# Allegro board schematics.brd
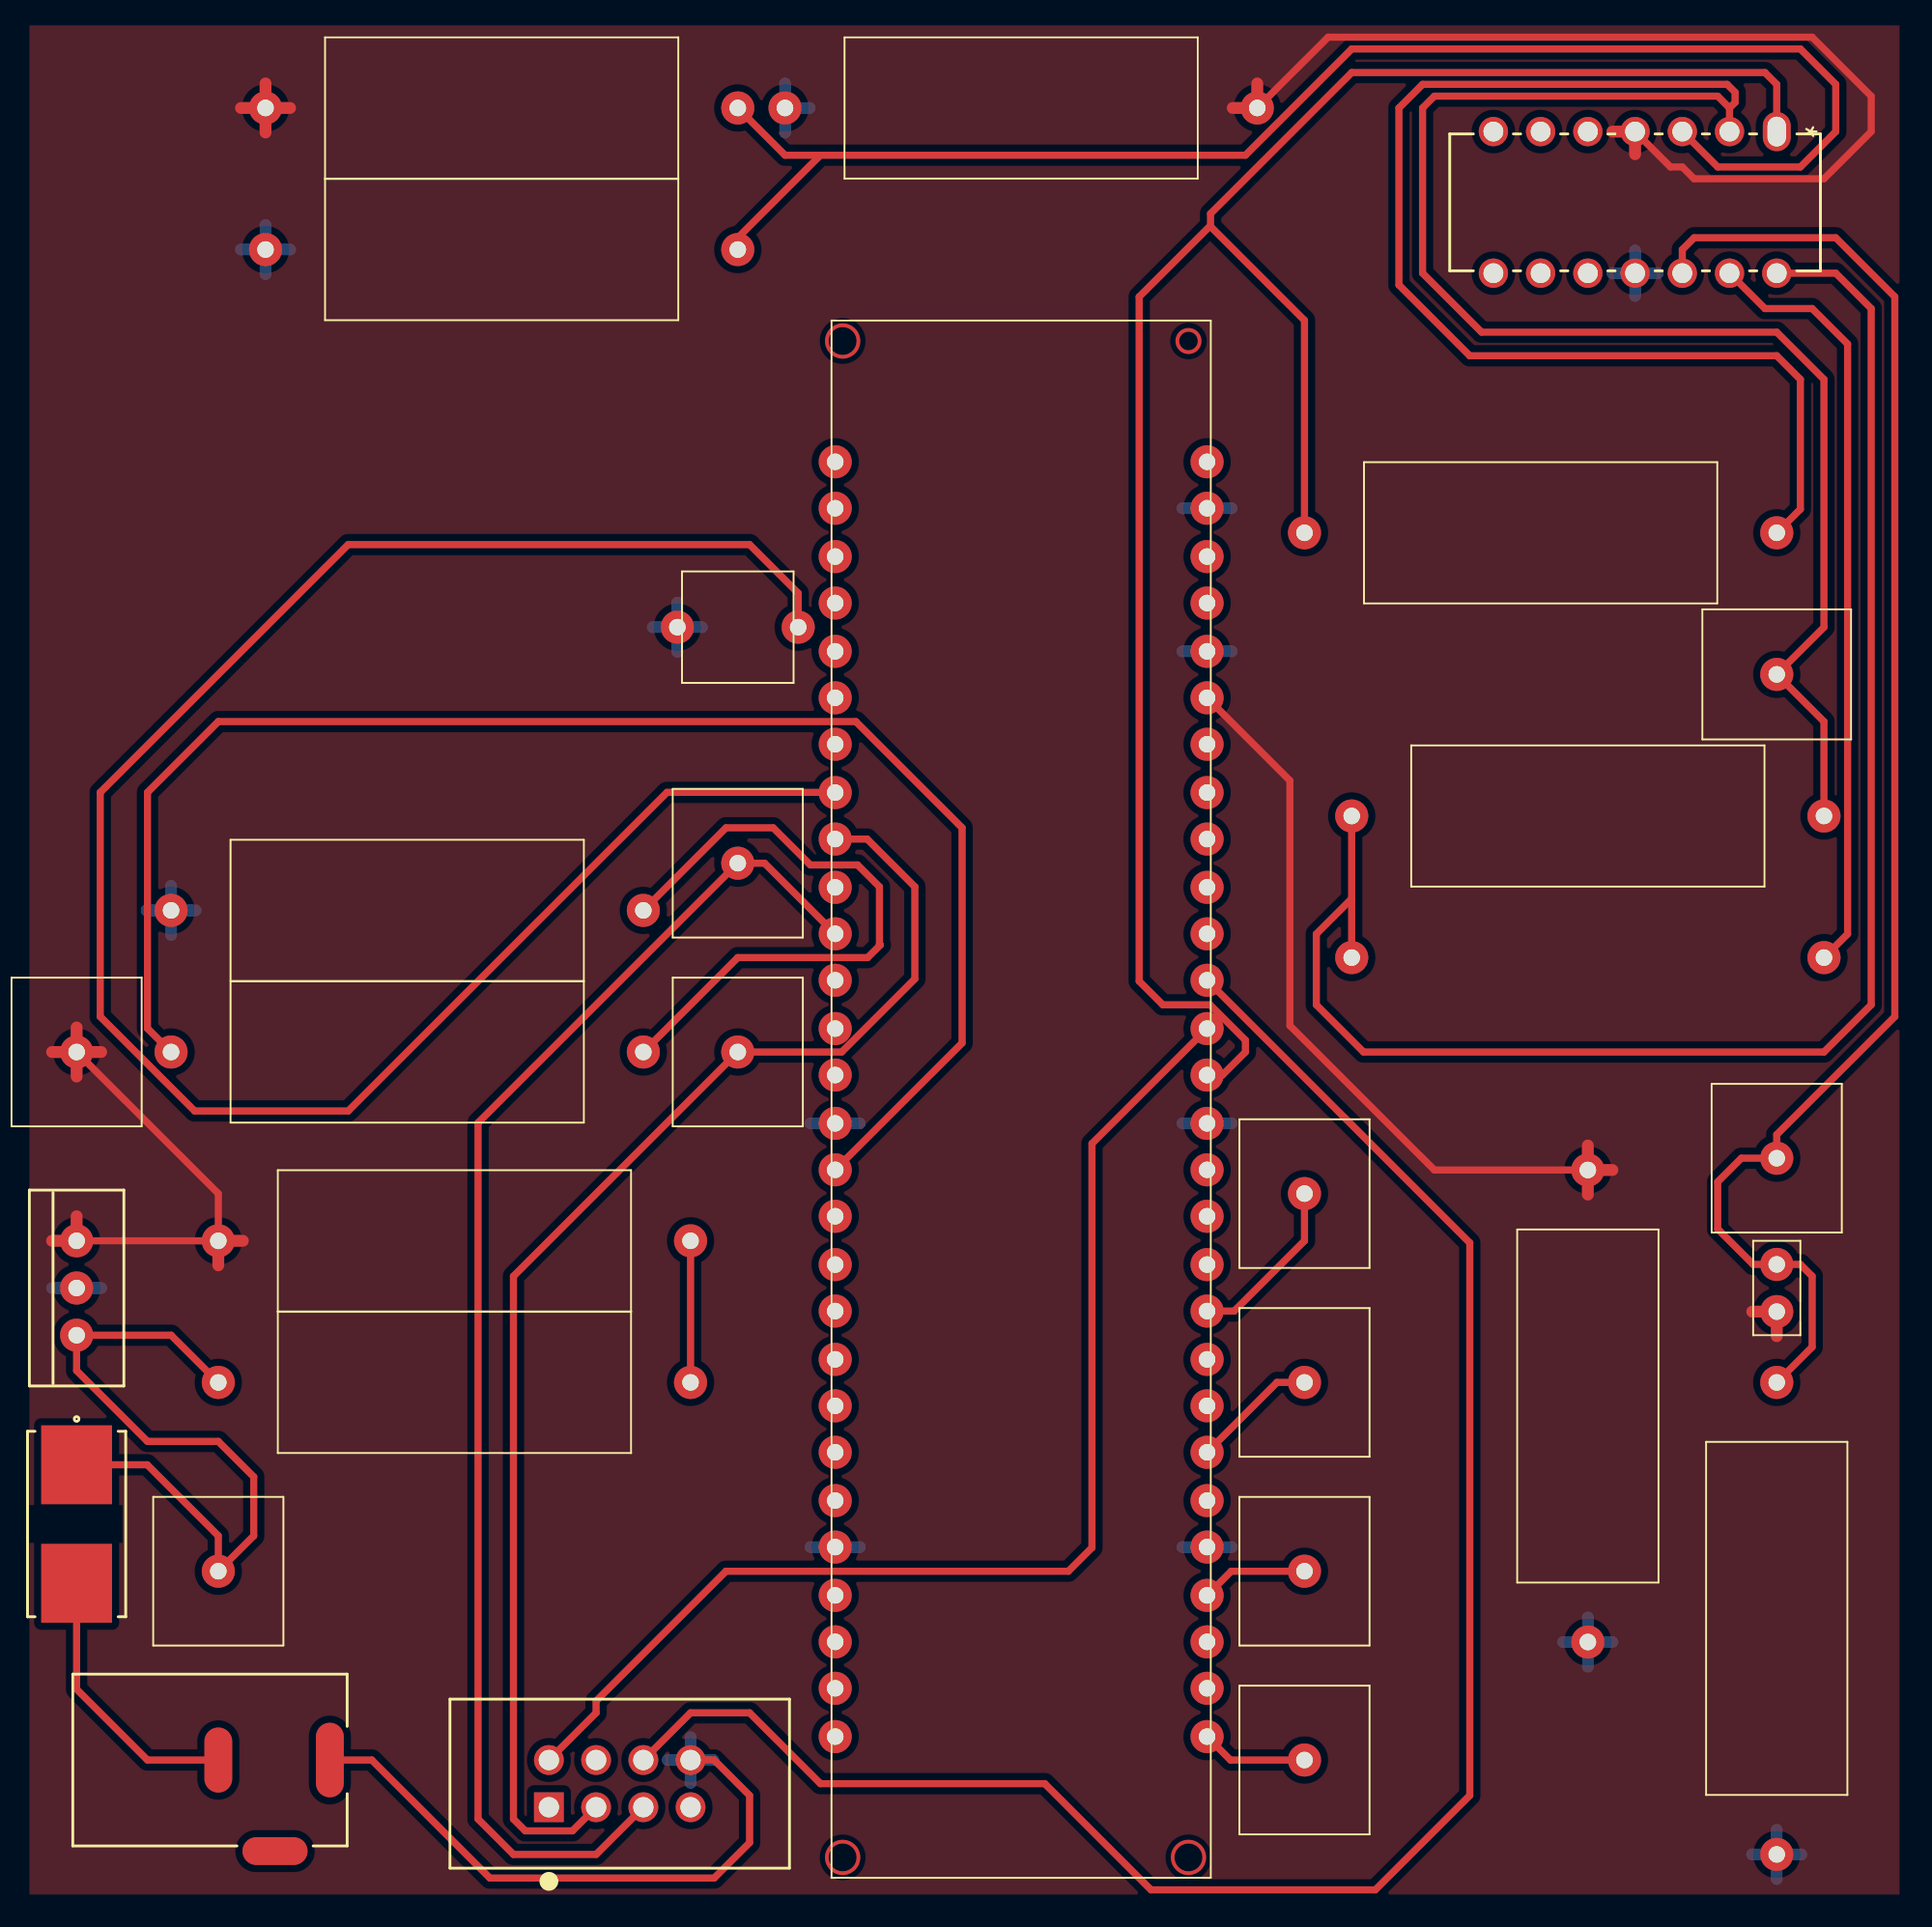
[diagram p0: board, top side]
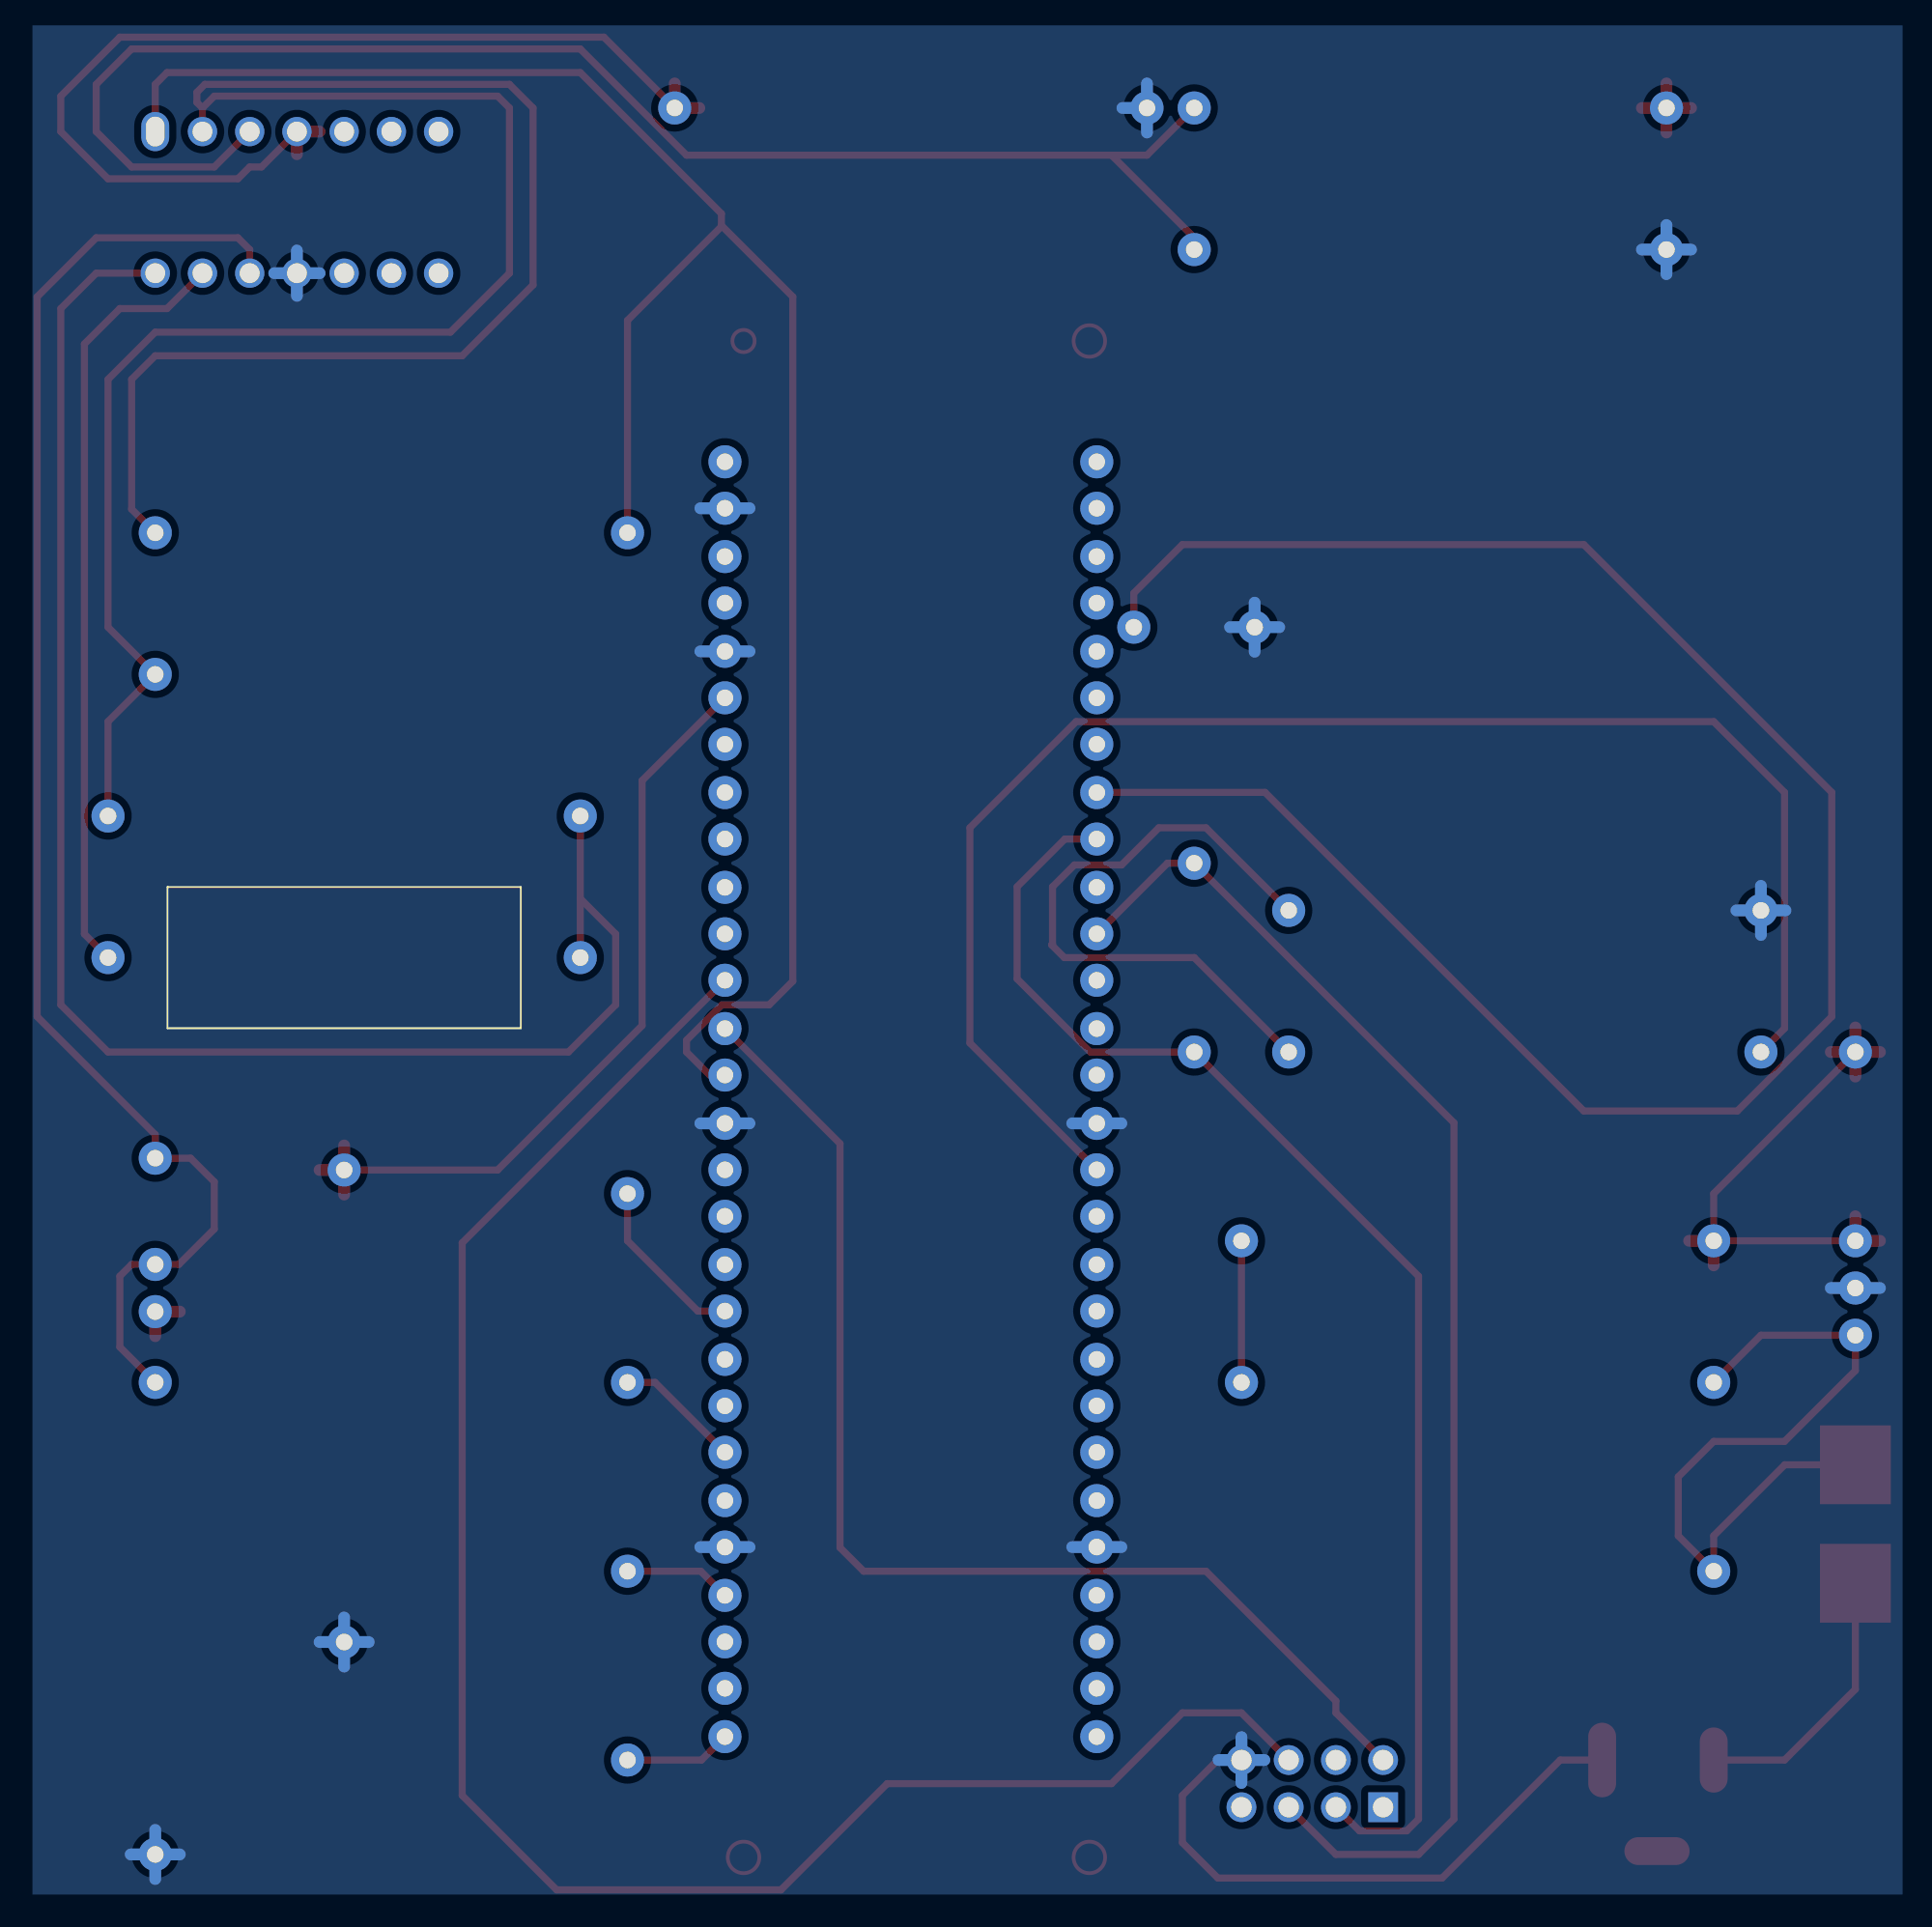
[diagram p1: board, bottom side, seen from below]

No outline. copper layers: TOP, BOTTOM. Coordinates in mm from the lowest, leftmost part position.

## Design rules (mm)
constraint set DEFAULT: min track width 0.127

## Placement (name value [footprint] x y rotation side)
C10  0.1  [RESISTOR_TH]  20.32 22.86 180 top
C11  CAP  [RESISTOR_TH]  20.32 30.48 180 top
C12  0.33 uF 50V  [RESISTOR_TH]  50.8 91.44 180 top
C13  CAP  [RESISTOR_TH]  81.28 21.59 270 top
D3  LED  [RESISTOR_TH]  17.78 48.26 0 top
F2  FUSE 1.5A  [FUSE_01550900M_LTF]  0 15.24 90 top
J22  TestPoint1  [CONNECTORONEPIN]  7.62 12.7 0 top
J23  TestPoint2  [CONNECTORONEPIN]  0 40.64 0 top
J25  TestPoint3  [CONNECTORONEPIN]  91.44 34.92 0 top
J27  TestPoint3  [CONNECTORONEPIN]  91.44 60.96 270 top
J28  TestPoint6  [CONNECTORONEPIN]  35.56 40.64 0 top
J29  SpareGPIO1  [CONNECTORONEPIN]  66.04 33.02 0 top
J30  SpareGPIO2  [CONNECTORONEPIN]  66.04 22.86 0 top
J31  SpareGPIO3  [CONNECTORONEPIN]  66.04 12.7 0 top
J32  SpareGPIO4  [CONNECTORONEPIN]  66.04 2.54 0 top
J33  TestPoint6  [CONNECTORONEPIN]  35.56 50.8 0 top
J34  CONN PCB 8_LS  [CONN_61200821621_WRE]  25.4 0 0 top
J35  B_JACK  [NEB21R_LMB]  7.62 2.54 0 top
PCND3  PIC18F57Q43 Curiosity Nano_LS  [56PINS-PIC]  50.8 38.1 0 top
R8  10k  [RESISTOR_TH]  91.44 10.16 270 top
R9  10k  [RESISTOR_TH]  81.28 45.72 180 bottom
R10  10k  [RESISTOR_TH]  81.28 53.34 0 top
R11  RESISTOR  [RESISTOR_TH]  78.74 68.58 0 top
R12  10k  [RESISTOR_TH]  22.86 91.44 0 top
R13  10k  [RESISTOR_TH]  22.86 83.82 180 top
R15  220  [RESISTOR_TH]  17.78 40.64 0 top
SW6  SW SPST  [PUSHBUTTON]  35.56 63.5 0 top
U11  VR_LS  [TO220-3_ONS]  0 25.4 90 top
U12  10kOhms-20kOhms  [HDR_1X02_2]  91.44 27.94 0 top
U14  MCP6004  [SOIC14-N_MC_MCH]  91.44 90.17 270 top

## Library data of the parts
C10 C11 = MKP1839410084HQ
C12 C13 = CAP
D3 = LED
F2 = FUSE/SM: User Part Number: PN; Tolerance: TOL
J22 J23 J25 J27-J33 = CON1
J34 = CONN PCB 8_2: User Part Number: PN; Tolerance: TOL
J35 = B_JACK: User Part Number: PN; Tolerance: TOL
PCND3 = PIC18F57Q10_18
R8-R13 R15 = RESISTOR
SW6 = SW SPST
U11 = VR_LS_11: User Part Number: PN; Tolerance: TOL
U12 = FLEX_SENSOR_FS_L_095_103_RH_0
U14 = MCP6004_0: User Part Number: PN; Tolerance: TOL

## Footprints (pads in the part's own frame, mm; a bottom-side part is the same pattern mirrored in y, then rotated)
56PINS-PIC
  round 1.778 hole 0.889: 1(-10,34.3) 2(-10,31.8) 3(-10,29.2) 4(-10,26.7) 5(-10,24.1) 6(-10,21.6) 7(-10,19.1) 8(-10,16.5) 9(-10,14) 10(-10,11.4) 11(-10,8.9) 12(-10,6.4) 13(-10,3.8) 14(-10,1.3) 15(-10,-1.3) 16(-10,-3.8) 17(-10,-6.3) 18(-10,-8.9) 19(-10,-11.4) 20(-10,-14) 21(-10,-16.5) 22(-10,-19) 23(-10,-21.6) 24(-10,-24.1) 25(-10,-26.7) 26(-10,-29.2) 27(-10,-31.7) 28(-10,-34.3) 29(10,-34.3) 30(10,-31.7) 31(10,-29.2) 32(10,-26.7) 33(10,-24.1) 34(10,-21.6) 35(10,-19) 36(10,-16.5) 37(10,-14) 38(10,-11.4) 39(10,-8.9) 40(10,-6.3) 41(10,-3.8) 42(10,-1.3) 43(10,1.3) 44(10,3.8) 45(10,6.4) 46(10,8.9) 47(10,11.4) 48(10,14) 49(10,16.5) 50(10,19.1) 51(10,21.6) 52(10,24.1) 53(10,26.7) 54(10,29.2) 55(10,31.8) 56(10,34.3)
CONN_61200821621_WRE
  rect 1.6x1.6 hole 1.092: 1(0,0)
  round 1.6 hole 1.092: 2(0,2.54) 3(2.54,0) 4(2.54,2.54) 5(5.08,0) 6(5.08,2.54) 7(7.62,0) 8(7.62,2.54)
CONNECTORONEPIN
  round 1.778 hole 0.889: 1(0,0)
FUSE_01550900M_LTF
  rect 4.242x3.81 smd: 1(-3.188,0) 2(3.188,0)
HDR_1X02_2
  round 1.778 hole 0.889: 1(0,1.27) 2(0,-1.27)
NEB21R_LMB
  oval 1.499x3.505 smd: 1(0,0)
  oval 1.499x4.013 smd: 2(6,0)
  oval 3.505x1.499 smd: 3(3.05,-4.9)
PUSHBUTTON
  round 1.778 hole 0.889: 1(-3.25,0) 2(3.25,0)
RESISTOR_TH
  round 1.778 hole 0.889: 1(-12.7,0) 2(12.7,0)
SOIC14-N_MC_MCH
  oval 2.108x1.499 hole 1.6x0.991: 1(0,0)
  round 1.575 hole 1.067: 2(0,-2.54) 3(0,-5.08) 4(0,-7.62) 5(0,-10.16) 6(0,-12.7) 7(0,-15.24) 8(7.62,-15.24) 9(7.62,-12.7) 10(7.62,-10.16) 11(7.62,-7.62) 12(7.62,-5.08) 13(7.62,-2.54) 14(7.62,0)
TO220-3_ONS
  round 1.778 hole 0.889: 1(0,0) 2(2.54,0) 3(5.08,0)

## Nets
5V: C11.2 C12.1 C13.1 J23.1 PCND3.51(VTG) R12.1 U11.3(VOUT) U12.2(VIN) U14.4
GND: C12.2 C13.2 D3.1(CATHODE) J34.8 J35.2 PCND3.15 PCND3.24 PCND3.33 PCND3.42 PCND3.52 PCND3.55 R8.2 R13.2 SW6.1 U11.2 U14.11(VSS)
FLEX_SENSOR_READINGS: PCND3.43 R11.1 U14.1
LED: PCND3.16 R15.1
PB_DEBUG: PCND3.8 SW6.2
PIN_2: J34.2 PCND3.44
PIN_3: J28.1 J34.3 PCND3.9
PIN_5: J33.1 J34.5 PCND3.11
PIN_6: J34.6 PCND3.45
STRAIN_OUT_RAW: J25.1 R8.1 U12.1 U14.12
N106824: C10.2 F2.2 J22.1 U11.1
N106956: C10.1 C11.1
N108303: R9.1 U14.13
N108331: R9.2 R10.1 U14.14
N108415: J27.1 R10.2 R11.2 U14.2
N108457: R12.2 R13.1 U14.3
N113032: J30.1 PCND3.35
N114337: J31.1 PCND3.32
N114341: J32.1 PCND3.29
N122941: F2.1 J35.1
N1137531: D3.2 R15.2
N11281237: J29.1 PCND3.38

Pads without a net: J34 1 4 7; J35 3; PCND3 1 2 3 4 5 6 7 10 12 13 14 17 18 19 20 21 22 23 25 26 27 28 30 31 34 36 37 39 40 41 46 47 48 49 50 53 54 56; U14 5 6 7 8 9 10

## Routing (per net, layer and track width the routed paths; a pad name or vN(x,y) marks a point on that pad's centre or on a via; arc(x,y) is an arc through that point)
5V: length 140.4
  TOP w0.127: PCND3.51 61.36,59.7
  TOP w0.381: C12.1 67.31,95.25 93.34,95.25 96.52,92.07 96.52,90.17 93.98,87.63 87,87.63 86.36,88.26 85.72,88.26 U14.4 ; PCND3.51 65.25,55.25 65.25,42.06 73.02,34.29 C13.1 ; J23.1 7.62,33.02 C11.2 U11.3
  TOP w0.635: C13.1 82.6,34.29 ; C13.1 81.28,35.61 ; C13.1 81.28,32.97 ; 82.6,90.17 U14.4 83.82,88.95 ; 7.62,29.16 C11.2 8.94,30.48 ; 91.44,25.35 U12.2 90.12,26.67 ; 0,39.32 J23.1 ; J23.1 0,41.96 ; J23.1 1.32,40.64 ; J23.1 -1.32,40.64 ; 62.18,91.44 C12.1 63.5,92.76 ; -1.32,30.48 U11.3 0,31.8 ; R12.1 11.48,91.44 ; R12.1 8.84,91.44 ; R12.1 10.16,90.12 ; R12.1 10.16,92.76
GND: length 91.2
  TOP w0.381: J34.8 34.29,2.54 36.19,0.63 36.19,-1.91 34.29,-3.81 22.22,-3.81 15.88,2.54 J35.2
  BOTTOM w0.635: R13.2 11.48,83.82 ; R13.2 10.16,85.14 ; R13.2 8.84,83.82 ; R13.2 10.16,82.5 ; C13.2 81.28,10.21 ; C13.2 82.6,8.89 ; C13.2 79.96,8.89 ; C13.2 81.28,7.57 ; 62.12,36.8 PCND3.42 59.48,36.8 ; 91.44,-3.86 R8.2 ; R8.2 90.12,-2.54 ; R8.2 91.44,-1.22 ; R8.2 92.76,-2.54 ; SW6.1 33.63,63.5 ; SW6.1 30.99,63.5 ; SW6.1 32.31,64.82 ; SW6.1 32.31,62.18 ; -1.32,27.94 U11.2 1.32,27.94 ; 5.08,46.94 D3.1 ; D3.1 6.4,48.26 ; D3.1 3.76,48.26 ; D3.1 5.08,49.58 ; U14.11 85.04,82.55 ; U14.11 83.82,81.33 ; U14.11 83.82,83.77 ; U14.11 82.6,82.55 ; C12.2 39.42,91.44 ; C12.2 38.1,90.12 ; C12.2 38.1,92.76 ; 31.79,2.54 J34.8 ; J34.8 33.02,3.77 ; J34.8 34.25,2.54 ; J34.8 33.02,1.31 ; 62.12,62.2 PCND3.52 59.48,62.2 ; 42.12,14 PCND3.24 39.48,14 ; 39.48,36.8 PCND3.15 42.12,36.8 ; 59.48,69.9 PCND3.55 62.12,69.9 ; 59.48,14 PCND3.33 62.12,14
FLEX_SENSOR_READINGS: length 108.2
  TOP w0.127: 60.99,85.12 60.99,85.06
  TOP w0.381: PCND3.43 61.62,39.4 62.87,40.64 62.87,41.28 60.96,43.18 58.42,43.18 57.15,44.45 57.15,81.28 60.99,85.12 60.99,85.75 68.58,93.34 90.81,93.34 91.44,92.71 U14.1 ; R11.1 66.04,80.01 60.99,85.06
LED: length 83.5
  TOP w0.381: PCND3.16 47.62,41.12 47.62,52.7 41.91,58.42 7.62,58.42 3.81,54.61 3.81,41.91 R15.1
PB_DEBUG: length 106.8
  TOP w0.381: SW6.2 38.81,65.33 36.19,67.94 14.61,67.94 1.27,54.61 1.27,42.54 6.35,37.46 14.61,37.46 31.75,54.61 40.09,54.61 40.1,54.6 PCND3.8
PIN_2: length 64.8
  TOP w0.381: PCND3.44 54.61,35.71 54.61,13.97 53.34,12.7 34.93,12.7 27.94,5.71 27.94,5.08 J34.2
PIN_3: length 73
  TOP w0.381: PCND3.9 42.52,52.1 45.08,49.53 45.08,44.58 41.15,40.64 J28.1 23.5,28.57 23.5,-0.64 24.13,-1.27 26.67,-1.27 J34.3
PIN_5: length 74.8
  TOP w0.381: PCND3.11 37,50.8 J33.1 21.59,36.83 21.59,-0.64 23.5,-2.54 27.94,-2.54 J34.5
PIN_6: length 101.3
  TOP w0.381: J34.6 33.02,5.08 36.19,5.08 40,1.27 52.07,1.27 57.78,-4.45 69.85,-4.45 74.93,0.63 74.93,30.37 PCND3.45
STRAIN_OUT_RAW: length 82.1
  TOP w0.381: U14.12 86.36,83.82 87,84.45 94.62,84.45 97.79,81.28 97.79,42.54 91.44,36.19 J25.1 89.53,34.92 88.26,33.66 88.26,31.11 90.17,29.21 U12.1 92.71,29.21 93.34,28.57 93.34,24.77 R8.1
N106824: length 39.4
  TOP w0.381: C10.2 5.08,25.4 U11.1 0,23.49 3.81,19.68 7.62,19.68 9.52,17.78 9.52,14.6 J22.1 7.62,14.6 3.8,18.43 F2.2
N106956: length 7.6
  TOP w0.381: C10.1 C11.1
N108303: length 41.5
  TOP w0.381: U14.13 90.81,80.64 93.34,80.64 95.25,78.74 95.25,46.99 R9.1
N108331: length 89.4
  TOP w0.381: R9.2 68.58,48.89 ; 68.58,48.89 R10.1 ; 68.58,48.89 66.68,46.99 66.68,43.18 69.21,40.64 93.98,40.64 96.52,43.18 96.52,80.64 94.62,82.55 U14.14
N108415: length 138.5
  TOP w0.381: R10.2 93.98,58.42 J27.1 93.98,63.5 93.98,76.83 91.44,79.38 75.56,79.38 72.39,82.55 72.39,91.44 73.02,92.07 88.26,92.07 88.9,91.44 ; 88.9,91.44 89.2,91.74 89.2,92.28 88.77,92.71 72.39,92.71 71.12,91.44 71.12,81.91 74.93,78.1 91.44,78.1 92.71,76.84 92.71,69.85 R11.2 ; 88.9,91.44 U14.2
N108457: length 82.6
  TOP w0.127: 35.56,84.45 R13.1
  TOP w0.381: 40,88.9 35.56,84.45 ; 40,88.9 38.1,88.9 R12.2 ; 40,88.9 62.87,88.9 68.58,94.61 92.71,94.61 94.62,92.71 94.62,90.17 92.71,88.26 88.26,88.26 U14.3
N113032: length 6.8
  TOP w0.381: J30.1 64.56,22.86 PCND3.35
N114337: length 5.8
  TOP w0.381: J31.1 62.1,12.7 PCND3.32
N114341: length 5.8
  TOP w0.381: J32.1 62.06,2.54 PCND3.29
N122941: length 14.9
  TOP w0.381: F2.1 0,6.35 3.81,2.54 J35.1
N1137531: length 34.1
  TOP w0.381: D3.2 34.93,52.7 37.46,52.7 39.46,50.71 42,50.71 43.18,49.53 43.18,46.45 43.23,46.4 42.55,45.72 35.56,45.72 R15.2
N11281237: length 9.3
  TOP w0.381: PCND3.38 62.26,26.7 66.04,30.48 J29.1

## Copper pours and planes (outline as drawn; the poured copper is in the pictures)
5V on TOP: 98.04,-4.7 98.04,95.88 -2.54,95.88 -2.54,-4.7
GND on BOTTOM: 98.04,-4.7 98.04,95.88 -2.54,95.88 -2.54,-4.7
